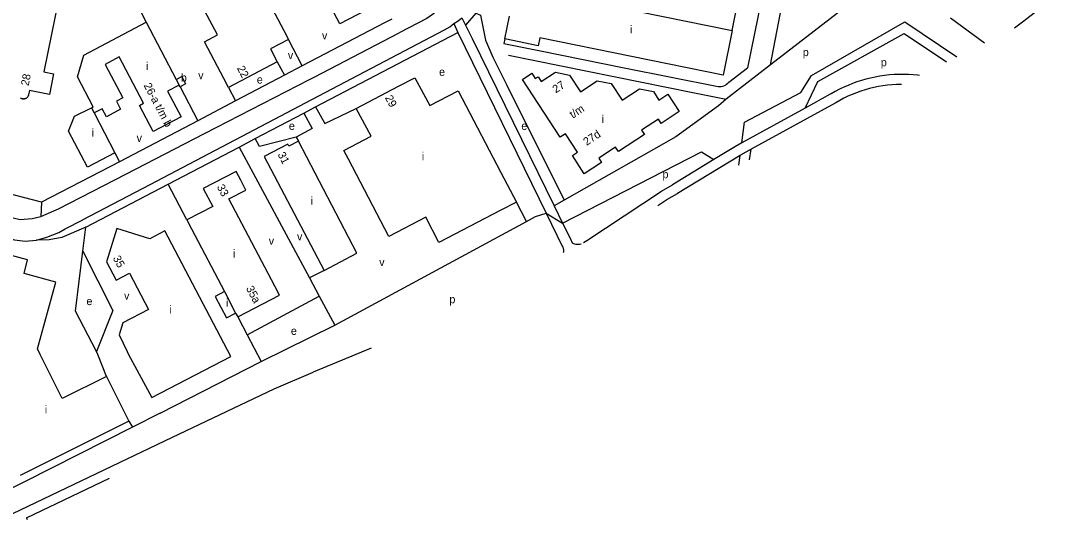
# Model space of a CAD drawing. Extents: x 157699 to 159683, y 381451 to 383293.
# Drawn here: x 158260 to 158773, y 381662 to 381917 of the extents above; entities that cross this region are included whole.
import ezdxf

# ---------------------------------------------------------------- set-up
doc = ezdxf.new("R2010")
doc.units = 0
for name, color, linetype in [('BLT_Basislijn', 7, 'Continuous'), ('BLT_Bebouwing', 7, 'Continuous'), ('BLT_Centroide', 7, 'Continuous'), ('BLT_Huisnummer', 7, 'Continuous'), ('BLT_Huisnummer_reeks', 7, 'Continuous'), ('BLT_Huisnummer_zonder_bebouwing', 7, 'Continuous'), ('BLT_Onderverdeling_panden', 7, 'Continuous'), ('BLT_Vlakafsluiter', 7, 'Continuous')]:
    doc.layers.add(name, color=color, linetype=linetype)

msp = doc.modelspace()

# ---------------------------------------------------------------- linework, layer by layer
at = {"layer": 'BLT_Basislijn'}
for p, q in [((158615.51, 381911.99), (158619.97, 381933.77)), ((158683.01, 381932.1), (158634.6, 381894.79)), ((158316.02, 381929.43), (158322.77, 381916.03)), ((158773.05, 381925.73), (158761.2, 381916.64)), ((158480.51, 381918.19), (158482.27, 381914.6)), ((158741.51, 381905.59), (158724.57, 381918.14)), ((158761.2, 381916.64), (158756.53, 381913.06)), ((158405.49, 381877.44), (158471.71, 381912.28)), ((158476.39, 381915.37), (158478.52, 381911.01)), ((158482.27, 381914.6), (158485.58, 381907.86)), ((158400.71, 381894.19), (158393.78, 381907.46)), ((158407.42, 381873.81), (158478.52, 381911.01)), ((158478.52, 381911.01), (158522.64, 381820.59)), ((158485.58, 381907.86), (158526.61, 381824.26)), ((158501.99, 381907.7), (158501.44, 381905.41)), ((158388.24, 381896.31), (158391.81, 381889.53)), ((158503.72, 381899.63), (158595.84, 381881.01)), ((158561.49, 381893.34), (158608.53, 381883.86)), ((158634.6, 381894.79), (158612.55, 381877.53)), ((158351.86, 381860.4), (158404.26, 381887.43)), ((158339.67, 381883.85), (158348.51, 381866.83)), ((158363.82, 381883.48), (158367.37, 381876.71)), ((158595.84, 381881.01), (158612.55, 381877.53)), ((158399.59, 381874.34), (158405.49, 381877.44)), ((158666.96, 381875.68), (158624.93, 381852.55)), ((158664.55, 381880.06), (158652.07, 381873.19)), ((158367.26, 381857.33), (158399.59, 381874.34)), ((158377.19, 381857.89), (158401.53, 381870.69)), ((158401.53, 381870.69), (158407.42, 381873.81)), ((158652.07, 381873.19), (158620.3, 381855.71)), ((158620.3, 381855.71), (158621.68, 381866.09)), ((158312.64, 381840.16), (158351.86, 381860.4)), ((158324.78, 381834.98), (158367.26, 381857.33)), ((158369.19, 381853.69), (158377.19, 381857.89)), ((158307.08, 381850.79), (158309.44, 381846.28)), ((158333.68, 381835.08), (158369.19, 381853.69)), ((158369.19, 381853.69), (158404.31, 381788.25)), ((158606.38, 381847.41), (158585.65, 381834.78)), ((158619.49, 381849.54), (158588.26, 381830.51)), ((158291.33, 381817.39), (158324.78, 381834.98)), ((158292.59, 381813.57), (158333.68, 381835.08)), ((158343.04, 381817.24), (158333.68, 381835.08)), ((158580.13, 381831.57), (158585.65, 381834.78)), ((158270.37, 381826.06), (158244.53, 381832.89)), ((158542.83, 381806.92), (158580.13, 381831.57)), ((158582.88, 381827.4), (158588.26, 381830.51)), ((158512.78, 381816.48), (158507.78, 381826.15)), ((158526.61, 381824.26), (158530.82, 381815.69)), ((158578.38, 381824.43), (158582.88, 381827.4)), ((158522.64, 381820.59), (158530.64, 381804.21)), ((158416.95, 381764.71), (158512.78, 381816.48)), ((158530.82, 381815.69), (158534.72, 381807.73)), ((158534.72, 381807.73), (158535.61, 381805.87)), ((158541.29, 381805.99), (158542.83, 381806.92)), ((158411.59, 381792.05), (158404.31, 381788.25)), ((158404.31, 381788.25), (158409.19, 381779.16)), ((158373.15, 381759.86), (158409.19, 381779.16)), ((158409.19, 381779.16), (158416.95, 381764.71)), ((158368.46, 381768.77), (158373.15, 381759.86)), ((158380.17, 381746.51), (158416.95, 381764.71)), ((158373.15, 381759.86), (158380.17, 381746.51)), ((158435.14, 381753.16), (158427.48, 381750)), ((158298.63, 381750), (158297.84, 381751.54)), ((158427.48, 381750), (158406.09, 381741.18)), ((158329.67, 381720.7), (158380.17, 381746.51)), ((158314.09, 381716.71), (158315.83, 381713.68)), ((158329.67, 381720.7), (158315.83, 381713.68)), ((158315.83, 381713.68), (158226.02, 381668.19)), ((158262.89, 381668.31), (158263.22, 381667.62))]:
    msp.add_line(p, q, dxfattribs=at)
for points in [[(158631.83, 381954.62), (158635.53, 381953.87), (158623.19, 381893.31)], [(158477.43, 381940.01), (158471.84, 381927.48), (158467.98, 381921.78), (158466.32, 381920.25), (158462.98, 381917.95), (158449.15, 381910.73)], [(158634.6, 381894.79), (158640.39, 381924.33)], [(158445.55, 381917.65), (158441.82, 381915.71), (158400.71, 381894.19)], [(158476.39, 381915.37), (158478.7, 381916.71), (158480.51, 381918.19)], [(158487.42, 381920.58), (158482.27, 381914.6)], [(158487.42, 381920.58), (158489.7, 381919.53), (158492.32, 381907.09), (158495.94, 381898.53), (158502.7, 381885.02), (158531.64, 381827.11)], [(158471.71, 381912.28), (158474.48, 381913.75), (158476.39, 381915.37)], [(158655.08, 381889.47), (158701.81, 381916.3), (158727.82, 381898.78)], [(158404.26, 381887.43), (158406.67, 381888.68), (158449.16, 381910.73)], [(158652.07, 381873.19), (158658.39, 381886.49), (158701.49, 381910.48), (158722.67, 381896.22)], [(158501.44, 381905.41), (158519.77, 381901.84), (158561.49, 381893.34)], [(158400.71, 381894.19), (158391.81, 381889.53)], [(158608.53, 381883.86), (158609.25, 381883.86), (158609.99, 381883.94), (158610.72, 381884.1), (158611.43, 381884.35), (158612.12, 381884.67), (158612.76, 381885.07), (158613.35, 381885.54), (158613.87, 381886.06), (158623.19, 381893.31)], [(158391.81, 381889.53), (158367.37, 381876.71)], [(158621.68, 381866.09), (158649.85, 381880.95), (158655.08, 381889.47)], [(158709.13, 381889.48), (158708.29, 381889.58), (158705.92, 381889.8), (158703.55, 381889.94), (158701.18, 381890), (158698.8, 381889.97), (158696.43, 381889.87), (158694.06, 381889.69), (158691.7, 381889.43), (158689.35, 381889.09), (158687.01, 381888.67), (158684.69, 381888.17), (158682.38, 381887.59), (158680.1, 381886.94), (158677.84, 381886.21), (158675.61, 381885.4), (158673.4, 381884.52), (158671.23, 381883.57), (158669.08, 381882.54), (158666.98, 381881.44), (158664.91, 381880.27), (158664.55, 381880.06)], [(158700.11, 381884.99), (158699.99, 381884.99), (158697.7, 381884.93), (158695.41, 381884.78), (158693.13, 381884.56), (158690.86, 381884.26), (158688.6, 381883.87), (158686.36, 381883.41), (158684.13, 381882.88), (158681.92, 381882.26), (158679.74, 381881.57), (158677.58, 381880.8), (158675.45, 381879.96), (158673.35, 381879.04), (158671.28, 381878.05), (158669.25, 381876.99), (158667.26, 381875.86), (158666.96, 381875.68)], [(158367.37, 381876.71), (158348.51, 381866.83)], [(158612.55, 381877.53), (158608.71, 381874.27), (158587.34, 381858.72), (158531.64, 381827.11)], [(158401.53, 381870.69), (158405.72, 381862.93), (158397.76, 381858.56)], [(158407.42, 381873.81), (158412.07, 381865.39), (158427.69, 381872.96)], [(158348.51, 381866.83), (158309.44, 381846.28)], [(158397.76, 381858.56), (158379.36, 381854.01), (158377.19, 381857.89)], [(158397.76, 381858.56), (158398.79, 381856.64)], [(158620.3, 381855.71), (158617.18, 381853.99), (158606.38, 381847.41)], [(158530.82, 381815.69), (158600.12, 381851.35), (158606.38, 381847.41)], [(158624.93, 381852.55), (158619.68, 381849.66), (158619.49, 381849.54)], [(158624.22, 381847.23), (158624.93, 381852.55)], [(158309.44, 381846.28), (158270.37, 381826.06)], [(158618.82, 381844.55), (158619.49, 381849.54)], [(158270.12, 381818.92), (158276.61, 381821.75), (158278.86, 381822.73), (158312.64, 381840.16)], [(158270.37, 381826.06), (158270.12, 381818.92)], [(158531.64, 381827.11), (158526.61, 381824.26)], [(158208.47, 381820.72), (158213.48, 381819.05), (158257.01, 381807.31), (158262.26, 381806.59), (158268.02, 381807.18)], [(158232.39, 381823.92), (158259.72, 381817.41), (158265.79, 381817.9)], [(158512.78, 381816.48), (158517.23, 381818.91), (158522.64, 381820.59)], [(158265.79, 381817.9), (158270.12, 381818.92)], [(158282.27, 381812.77), (158291.09, 381817.26), (158291.33, 381817.39)], [(158292.59, 381813.57), (158280.63, 381808.53), (158274.21, 381807.32), (158268.02, 381807.18)], [(158268.02, 381807.18), (158273.14, 381808.61), (158279.03, 381810.9), (158282.27, 381812.77)], [(158291.13, 381801.67), (158292.59, 381813.57)], [(158530.64, 381804.21), (158530.9, 381803.63), (158531.08, 381803.02), (158531.19, 381802.39), (158531.22, 381801.75), (158531.17, 381801.12), (158531.13, 381800.91)], [(158535.61, 381805.87), (158536.16, 381805.56), (158536.76, 381805.32), (158537.38, 381805.16), (158538.01, 381805.08), (158538.65, 381805.07), (158539.28, 381805.15), (158539.9, 381805.3), (158540.1, 381805.38)], [(158541.18, 381805.92), (158541.29, 381805.99)], [(158297.84, 381751.54), (158287.45, 381771.64), (158291.13, 381801.67)], [(158291.13, 381801.67), (158306.15, 381772.02), (158297.84, 381751.54)], [(158302.92, 381739.07), (158298.63, 381750)], [(158335.95, 381708.7), (158386.64, 381732.88), (158406.09, 381741.18)], [(158237.13, 381661.56), (158335.95, 381708.7)], [(158262.89, 381668.31), (158304.48, 381688.15)]]:
    msp.add_lwpolyline(points, dxfattribs=at)
at = {"layer": 'BLT_Bebouwing'}
for p, q in [((158526.98, 381929.97), (158615.51, 381911.99)), ((158501.99, 381907.7), (158504.27, 381919.1)), ((158305.1, 381906.69), (158305.06, 381906.76)), ((158339.67, 381883.85), (158339.26, 381884.62)), ((158260.06, 381878.1), (158259.9, 381878.21)), ((158260.47, 381877.89), (158260.27, 381877.98)), ((158260.91, 381877.76), (158260.68, 381877.82)), ((158261.36, 381877.71), (158261.14, 381877.73)), ((158261.82, 381877.74), (158261.59, 381877.72)), ((158262.26, 381877.84), (158262.03, 381877.78)), ((158262.26, 381877.84), (158262.48, 381877.93)), ((158262.68, 381878.02), (158262.48, 381877.93)), ((158262.88, 381878.15), (158263.06, 381878.28)), ((158263.39, 381878.59), (158263.24, 381878.43)), ((158263.67, 381878.96), (158263.54, 381878.78)), ((158263.87, 381879.36), (158263.78, 381879.18)), ((158264, 381879.82), (158263.95, 381879.64)), ((158296.74, 381870.71), (158307.08, 381850.79)), ((158365.01, 381749.08), (158332.06, 381811.8)), ((158367.45, 381770.7), (158368.46, 381768.77)), ((158309.19, 381759.79), (158313.17, 381751.52)), ((158280.77, 381728.01), (158269.81, 381750)), ((158313.17, 381751.52), (158313.99, 381750)), ((158313.99, 381750), (158325.61, 381728.48)), ((158325.61, 381728.48), (158365.01, 381749.08))]:
    msp.add_line(p, q, dxfattribs=at)
for points in [[(158440.98, 381926.41), (158419.52, 381915.24), (158399.38, 381953.65)], [(158371.01, 381950.82), (158391.45, 381911.89), (158393.78, 381907.46)], [(158280.97, 381937.29), (158271.56, 381891.25), (158276.45, 381890.19), (158274.36, 381879.91), (158264.45, 381881.89), (158264, 381879.82)], [(158363.82, 381883.48), (158361.5, 381887.9), (158351.85, 381906.33), (158358.3, 381909.71), (158344.12, 381936.7)], [(158295.38, 381873.33), (158296.27, 381873.8), (158288.4, 381888.79), (158291.54, 381899.68), (158322.77, 381916.03)], [(158322.77, 381916.03), (158337.74, 381887.45)], [(158615.51, 381911.99), (158610.97, 381889.66), (158519.36, 381908.3)], [(158393.78, 381907.46), (158384.85, 381902.77), (158388.24, 381896.31)], [(158519.36, 381908.3), (158518.52, 381904.34), (158501.99, 381907.7)], [(158339.26, 381884.62), (158333.42, 381881.56), (158340.15, 381868.71), (158326.25, 381861.44), (158319.4, 381874.52), (158321.4, 381875.56), (158309.29, 381898.7), (158302.24, 381895), (158311.05, 381878.21), (158307.88, 381876.55), (158309.96, 381872.57), (158302.88, 381868.86), (158300.79, 381872.83), (158296.74, 381870.71)], [(158388.24, 381896.31), (158363.82, 381883.48)], [(158510.74, 381887.42), (158515.44, 381890.53), (158517.16, 381887.94), (158518.51, 381888.81), (158520.07, 381886.43), (158527.2, 381891.1), (158534.19, 381889.64), (158539.69, 381881.32), (158548.02, 381886.82), (158555.04, 381885.41), (158560.51, 381877.07), (158569.26, 381882.84), (158576.21, 381881.41), (158578.96, 381877.19), (158583.44, 381880.13), (158589.12, 381871.5), (158580.02, 381865.51), (158578.63, 381867.62), (158570.25, 381862.12), (158571.64, 381860.01), (158558.65, 381851.49), (158557.26, 381853.59), (158548.85, 381848.07), (158550.26, 381845.98), (158541.65, 381840.33), (158535.67, 381849.44), (158538.23, 381851.1), (158532.17, 381860.24), (158529.64, 381858.61), (158510.74, 381887.42)], [(158337.74, 381887.45), (158340.52, 381888.92), (158342.43, 381885.27), (158339.67, 381883.85)], [(158427.69, 381872.96), (158448.87, 381884.03), (158457.02, 381888.27), (158464.39, 381874.47), (158478.6, 381881.81), (158500, 381840.99), (158507.78, 381826.15)], [(158260.06, 381878.1), (158260.09, 381878.07), (158260.27, 381877.98)], [(158260.47, 381877.89), (158260.5, 381877.88), (158260.68, 381877.82)], [(158260.91, 381877.76), (158260.94, 381877.75), (158261.14, 381877.73)], [(158261.36, 381877.71), (158261.39, 381877.7), (158261.59, 381877.72)], [(158261.82, 381877.74), (158261.85, 381877.74), (158262.03, 381877.78)], [(158262.68, 381878.02), (158262.71, 381878.04), (158262.88, 381878.15)], [(158263.06, 381878.28), (158263.09, 381878.29), (158263.24, 381878.43)], [(158263.39, 381878.59), (158263.42, 381878.61), (158263.54, 381878.78)], [(158263.67, 381878.96), (158263.68, 381878.98), (158263.78, 381879.18)], [(158263.87, 381879.36), (158263.88, 381879.4), (158263.95, 381879.64)], [(158307.08, 381850.79), (158293.38, 381843.6), (158283.94, 381861.7), (158286.98, 381869.04), (158295.38, 381873.33)], [(158421.51, 381852), (158435.08, 381859.16), (158427.69, 381872.96)], [(158398.79, 381856.64), (158394.09, 381854.1), (158393.54, 381855.13), (158381.76, 381848.97), (158411.59, 381792.05)], [(158411.59, 381792.05), (158428.07, 381800.65), (158398.79, 381856.64)], [(158507.78, 381826.15), (158500, 381822.08), (158469.04, 381805.91), (158462.39, 381818.6), (158444.04, 381808.99), (158423.83, 381847.57), (158421.51, 381852)], [(158368.46, 381768.77), (158389.29, 381779.73), (158386.96, 381784.16), (158364.08, 381827.77), (158372.58, 381832.21), (158370.01, 381837.11), (158367.68, 381841.54), (158351.27, 381832.92), (158355.97, 381824.02), (158343.04, 381817.24)], [(158343.04, 381817.24), (158345.36, 381812.81), (158361.83, 381781.42)], [(158332.06, 381811.8), (158324.54, 381807.89), (158308.07, 381813.04), (158302.95, 381796.32), (158307.68, 381787.19), (158314.42, 381790.73), (158323.96, 381772.54), (158311.05, 381765.75), (158309.19, 381759.79)], [(158269.81, 381750), (158268.43, 381752.77), (158277.65, 381786.21), (158261.76, 381790.51), (158263.5, 381797.38), (158246.68, 381801.84), (158244.64, 381794.18), (158242.34, 381794.76), (158230.44, 381750)], [(158361.83, 381781.42), (158357.28, 381779.03), (158362.9, 381768.32), (158367.45, 381770.7)], [(158302.92, 381739.07), (158280.77, 381728.01)], [(158302.92, 381739.07), (158314.09, 381716.71)], [(158314.09, 381716.71), (158259.76, 381689.57)]]:
    msp.add_lwpolyline(points, dxfattribs=at)
at = {"layer": 'BLT_Onderverdeling_panden'}
for p, q in [((158337.74, 381887.45), (158339.26, 381884.62)), ((158295.38, 381873.33), (158296.74, 381870.71)), ((158361.83, 381781.42), (158367.45, 381770.7))]:
    msp.add_line(p, q, dxfattribs=at)
at = {"layer": 'BLT_Vlakafsluiter'}
msp.add_line((158522.64, 381820.59), (158530.82, 381815.69), dxfattribs=at)

# ---------------------------------------------------------------- texts
at = {"layer": 'BLT_Centroide'}
for s, p in [('i', (158564.52, 381910.52)), ('v', (158410.58, 381907.5)), ('p', (158650.81, 381899.12)), ('i', (158322.62, 381892.17)), ('v', (158393.54, 381897.63)), ('p', (158689.78, 381894.07)), ('e', (158469.07, 381889.25)), ('b', (158340.08, 381886.38)), ('v', (158348.74, 381887.58)), ('e', (158378.01, 381885.41)), ('e', (158394.03, 381862.25)), ('e', (158510.18, 381862.28)), ('i', (158550.35, 381865.72)), ('i', (158295.52, 381858.89)), ('v', (158317.98, 381856.23)), ('i', (158460.45, 381847.09)), ('p', (158580.7, 381838.09)), ('i', (158404.91, 381824.86)), ('v', (158398.11, 381807.03)), ('v', (158383.98, 381804.85)), ('i', (158366.16, 381798.47)), ('v', (158439.17, 381794.17)), ('v', (158311.69, 381777.36)), ('p', (158474.24, 381775.63)), ('e', (158292.91, 381774.69)), ('i', (158334.23, 381770.45)), ('i', (158362.67, 381773.84)), ('e', (158395.05, 381759.8)), ('i', (158272.11, 381720.56))]:
    msp.add_text(s, height=4, dxfattribs=at).set_placement(p)
at = {"layer": 'BLT_Huisnummer'}
for s, rotation, p in [('22', 297.6566, (158367.98, 381893.08)), ('28', 78.4823, (158263.97, 381884.01)), ('29', 298.1595, (158441.91, 381878.36)), ('31', 298.1595, (158388.27, 381849.98)), ('35', 298.1641, (158305.96, 381798.19))]:
    msp.add_text(s, height=4, rotation=rotation, dxfattribs=at).set_placement(p)
at = {"layer": 'BLT_Huisnummer_reeks'}
for s, rotation, p in [('27', 33.2408, (158527.37, 381880.45)), ('t/m', 33.4081, (158535.89, 381867.78)), ('27d', 33.4155, (158542.77, 381854.22)), ('33', 297.8384, (158357.93, 381833.78)), ('35a', 297.6743, (158372.49, 381783.09))]:
    msp.add_text(s, height=4, rotation=rotation, dxfattribs=at).set_placement(p)
at = {"layer": 'BLT_Huisnummer_zonder_bebouwing'}
msp.add_text('26-a t/m b', height=4, rotation=297.7109, dxfattribs=at).set_placement((158321.37, 381884.51))

doc.saveas('drawing.dxf')
